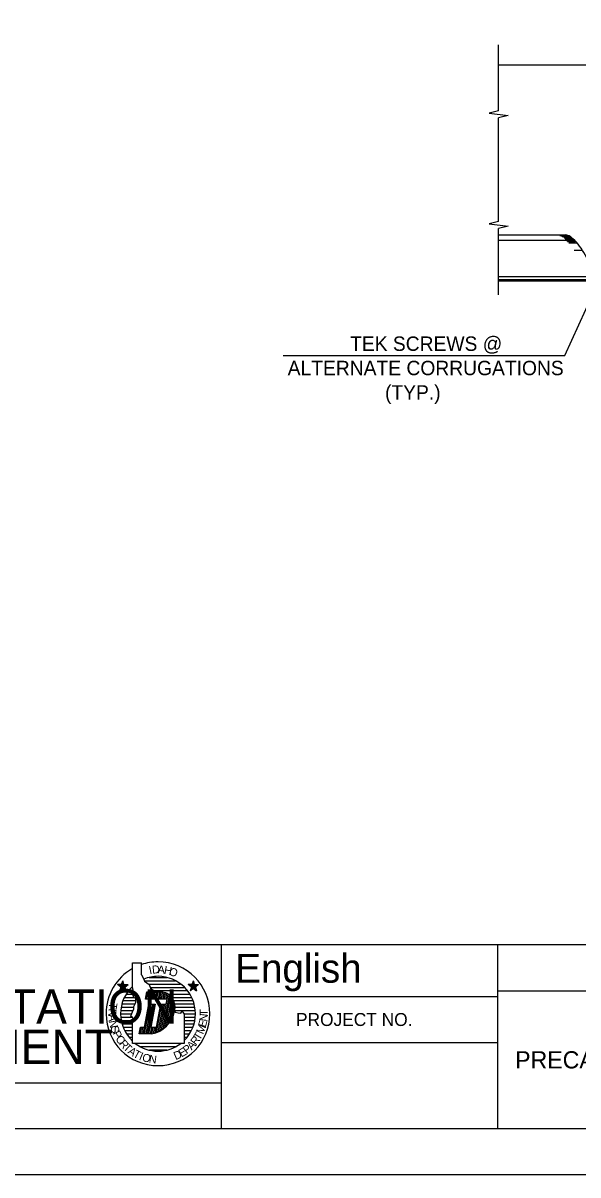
# Model space of a CAD drawing. Extents: x 0 to 34, y 0 to 23.5.
# Drawn here: x 17.1 to 23.12, y 0 to 12.5 of the extents above; entities that cross this region are included whole.
import ezdxf

# ---------------------------------------------------------------- set-up
doc = ezdxf.new("R2010")
doc.units = 0
for name, color, linetype in [('BORDER_ANNO_Cutsheet', 7, 'Continuous'), ('BRDG_ANNO_Anno-Sheet', 7, 'Continuous'), ('BRDG_ANNO_General-Notes', 7, 'Continuous'), ('BRDG_BASE_Obj-Line', 7, 'Continuous')]:
    doc.layers.add(name, color=color, linetype=linetype)

msp = doc.modelspace()

# ---------------------------------------------------------------- linework, layer by layer
at = {"layer": 'BORDER_ANNO_Cutsheet'}
msp.add_lwpolyline([(0, 22), (34, 22), (34, 0), (0, 0)], close=True, dxfattribs=at)
at = {"layer": 'BRDG_ANNO_Anno-Sheet'}
for p, q in [((1.5, 2.5), (19.25, 2.5)), ((19.25, 0.5), (19.25, 2.5)), ((19.25, 2.5), (33.5, 2.5)), ((22.25, 0.5), (22.25, 2.5)), ((18.284, 2.042), (18.284, 2.303)), ((18.284, 2.303), (18.383, 2.303)), ((18.383, 2.173), (18.383, 2.303)), ((18.383, 2.173), (18.409, 2.126)), ((18.409, 2.126), (18.414, 2.105)), ((18.465, 2.144), (18.658, 2.144)), ((18.201, 2.04), (18.122, 2.066)), ((18.166, 2.066), (18.122, 2.066)), ((18.157, 2.04), (18.122, 2.066)), ((18.193, 2.066), (18.144, 1.998)), ((18.157, 2.04), (18.144, 1.998)), ((18.179, 2.024), (18.144, 1.998)), ((18.157, 2.04), (18.237, 2.066)), ((18.166, 2.066), (18.179, 2.107)), ((18.166, 2.066), (18.215, 1.998)), ((18.179, 2.024), (18.179, 2.107)), ((18.193, 2.066), (18.179, 2.107)), ((18.179, 2.024), (18.215, 1.998)), ((18.193, 2.066), (18.237, 2.066)), ((18.201, 2.04), (18.237, 2.066)), ((18.201, 2.04), (18.215, 1.998)), ((18.242, 2.001), (18.294, 2.001)), ((18.274, 2.036), (18.286, 2.036)), ((18.294, 2.006), (18.284, 2.042)), ((18.294, 1.975), (18.294, 2.006)), ((18.414, 2.105), (18.466, 2.069)), ((18.417, 2.108), (18.751, 2.108)), ((18.465, 2.072), (18.807, 2.072)), ((18.466, 2.069), (18.482, 2.027)), ((18.479, 2.036), (18.851, 2.036)), ((18.482, 2.027), (18.534, 1.986)), ((18.516, 2.001), (18.883, 2.001)), ((18.968, 2.04), (18.888, 2.066)), ((18.924, 2.04), (18.888, 2.066)), ((18.932, 2.066), (18.888, 2.066)), ((18.959, 2.066), (18.91, 1.998)), ((18.924, 2.04), (18.91, 1.998)), ((18.946, 2.024), (18.91, 1.998)), ((18.924, 2.04), (19.002, 2.066)), ((18.932, 2.066), (18.946, 2.107)), ((18.932, 2.066), (18.981, 1.998)), ((18.946, 2.024), (18.946, 2.107)), ((18.959, 2.066), (18.946, 2.107)), ((18.946, 2.024), (18.981, 1.998)), ((18.959, 2.066), (19.002, 2.066)), ((18.968, 2.04), (19.002, 2.066)), ((18.968, 2.04), (18.981, 1.998)), ((18.181, 1.892), (18.319, 1.892)), ((18.197, 1.928), (18.298, 1.928)), ((18.217, 1.964), (18.293, 1.964)), ((18.294, 1.949), (18.294, 1.975)), ((18.3, 1.928), (18.294, 1.949)), ((18.321, 1.917), (18.3, 1.928)), ((18.31, 1.85), (18.321, 1.876)), ((18.321, 1.891), (18.321, 1.917)), ((18.321, 1.876), (18.321, 1.891)), ((18.425, 1.907), (18.441, 1.986)), ((18.661, 1.907), (18.425, 1.907)), ((18.439, 1.907), (18.454, 1.986)), ((18.441, 1.986), (18.613, 1.986)), ((18.455, 1.907), (18.47, 1.986)), ((18.471, 1.907), (18.486, 1.986)), ((18.487, 1.907), (18.502, 1.986)), ((18.502, 1.907), (18.517, 1.986)), ((18.519, 1.907), (18.533, 1.986)), ((18.534, 1.907), (18.549, 1.986)), ((18.551, 1.907), (18.565, 1.986)), ((18.566, 1.907), (18.581, 1.986)), ((18.582, 1.907), (18.597, 1.986)), ((18.598, 1.907), (18.613, 1.986)), ((18.599, 1.574), (18.672, 1.962)), ((18.614, 1.907), (18.628, 1.981)), ((18.617, 1.586), (18.686, 1.952)), ((18.63, 1.907), (18.643, 1.977)), ((18.636, 1.601), (18.699, 1.939)), ((18.646, 1.907), (18.657, 1.97)), ((18.652, 1.855), (18.661, 1.907)), ((18.656, 1.619), (18.712, 1.924)), ((18.669, 1.964), (18.907, 1.964)), ((18.676, 1.64), (18.725, 1.906)), ((18.697, 1.669), (18.737, 1.882)), ((18.71, 1.928), (18.927, 1.928)), ((18.732, 1.892), (18.943, 1.892)), ((19.25, 1.938), (22.25, 1.938)), ((22.25, 2), (30.25, 2)), ((18.157, 1.784), (18.291, 1.784)), ((18.162, 1.821), (18.298, 1.821)), ((18.171, 1.856), (18.311, 1.856)), ((18.269, 1.725), (18.279, 1.751)), ((18.279, 1.751), (18.284, 1.772)), ((18.284, 1.772), (18.3, 1.803)), ((18.3, 1.829), (18.31, 1.85)), ((18.3, 1.803), (18.3, 1.829)), ((18.414, 1.605), (18.461, 1.855)), ((18.416, 1.532), (18.477, 1.855)), ((18.433, 1.532), (18.493, 1.855)), ((18.448, 1.532), (18.509, 1.855)), ((18.461, 1.855), (18.53, 1.855)), ((18.464, 1.532), (18.525, 1.855)), ((18.53, 1.855), (18.483, 1.605)), ((18.544, 1.605), (18.591, 1.855)), ((18.547, 1.547), (18.604, 1.855)), ((18.564, 1.555), (18.62, 1.855)), ((18.581, 1.563), (18.636, 1.855)), ((18.591, 1.855), (18.652, 1.855)), ((18.722, 1.718), (18.746, 1.845)), ((18.741, 1.777), (18.748, 1.766)), ((18.742, 1.784), (18.968, 1.784)), ((18.744, 1.856), (18.954, 1.856)), ((18.747, 1.821), (18.962, 1.821)), ((18.748, 1.766), (18.779, 1.761)), ((18.779, 1.761), (18.811, 1.756)), ((18.811, 1.756), (18.826, 1.777)), ((18.826, 1.777), (18.847, 1.746)), ((18.156, 1.748), (18.277, 1.748)), ((18.158, 1.712), (18.281, 1.712)), ((18.163, 1.676), (18.298, 1.676)), ((18.171, 1.641), (18.284, 1.641)), ((18.284, 1.709), (18.269, 1.725)), ((18.294, 1.694), (18.284, 1.709)), ((18.284, 1.652), (18.3, 1.667)), ((18.284, 1.427), (18.284, 1.652)), ((18.3, 1.683), (18.294, 1.694)), ((18.3, 1.667), (18.3, 1.683)), ((18.845, 1.748), (18.969, 1.748)), ((18.847, 1.746), (18.847, 1.427)), ((18.847, 1.676), (18.962, 1.676)), ((18.847, 1.641), (18.954, 1.641)), ((18.848, 1.712), (18.967, 1.712)), ((18.184, 1.604), (18.282, 1.604)), ((18.199, 1.568), (18.282, 1.568)), ((18.22, 1.532), (18.283, 1.532)), ((18.359, 1.532), (18.373, 1.605)), ((18.492, 1.532), (18.359, 1.532)), ((18.369, 1.532), (18.383, 1.605)), ((18.373, 1.605), (18.414, 1.605)), ((18.385, 1.532), (18.399, 1.605)), ((18.401, 1.532), (18.414, 1.605)), ((18.48, 1.532), (18.494, 1.605)), ((18.483, 1.605), (18.544, 1.605)), ((18.496, 1.532), (18.51, 1.605)), ((18.513, 1.537), (18.526, 1.605)), ((18.53, 1.542), (18.541, 1.605)), ((18.847, 1.604), (18.941, 1.604)), ((18.847, 1.568), (18.925, 1.568)), ((18.847, 1.532), (18.905, 1.532)), ((18.246, 1.496), (18.282, 1.496)), ((18.277, 1.461), (18.284, 1.461)), ((18.847, 1.427), (18.284, 1.427)), ((18.751, 1.391), (18.372, 1.391)), ((18.847, 1.496), (18.88, 1.496)), ((19.25, 1.438), (22.25, 1.438)), ((18.659, 1.356), (18.468, 1.356)), ((14, 1), (19.25, 1))]:
    msp.add_line(p, q, dxfattribs=at)
msp.add_lwpolyline([(1.5, 21.5), (33.5, 21.5), (33.5, 0.5), (1.5, 0.5)], close=True, dxfattribs=at)
for centre, radius, start, end in [((18.562, 1.75), 0.563, 90, 108.596), ((18.562, 1.75), 0.563, 0, 90), ((18.562, 1.75), 0.563, 119.6331, 180), ((18.562, 1.75), 0.406, 90, 112.1452), ((18.562, 1.75), 0.406, 0, 90), ((18.562, 1.75), 0.406, 133.1926, 180), ((18.583, 1.824), 0.164, 343.4981, 79.7362), ((18.435, 1.838), 0.312, 280.6479, 348.7719), ((18.562, 1.75), 0.563, 180, 270), ((18.562, 1.75), 0.406, 180.2644, 226.7946), ((18.562, 1.75), 0.563, 270, 0), ((18.562, 1.75), 0.406, 314.427, 0), ((18.562, 1.75), 0.406, 232.5658, 270), ((18.562, 1.75), 0.406, 270, 307.4536)]:
    msp.add_arc(centre, radius, start, end, dxfattribs=at)
at = {"layer": 'BRDG_ANNO_General-Notes'}
for p, q in [((22.976, 8.893), (23.281, 9.56)), ((19.92, 8.893), (22.976, 8.893))]:
    msp.add_line(p, q, dxfattribs=at)
at = {"layer": 'BRDG_BASE_Obj-Line'}
for p, q in [((22.258, 11.551), (22.258, 12.267)), ((22.258, 12.05), (26.139, 12.05)), ((22.258, 11.551), (22.156, 11.525)), ((22.156, 11.525), (22.361, 11.5)), ((22.361, 11.5), (22.258, 11.474)), ((22.258, 10.348), (22.258, 11.474)), ((22.258, 10.348), (22.156, 10.323)), ((22.156, 10.323), (22.361, 10.297)), ((22.361, 10.297), (22.258, 10.272)), ((22.258, 9.555), (22.258, 10.272)), ((22.258, 10.205), (22.985, 10.205)), ((22.258, 10.148), (23.077, 10.148)), ((22.922, 10.197), (23.003, 10.197)), ((22.936, 10.192), (23.018, 10.192)), ((22.946, 10.187), (23.03, 10.187)), ((22.964, 10.18), (23.047, 10.18)), ((22.974, 10.17), (23.057, 10.17)), ((22.979, 10.162), (23.062, 10.162)), ((22.988, 10.156), (23.072, 10.156)), ((22.998, 10.141), (23.079, 10.141)), ((23.005, 10.133), (23.089, 10.133)), ((23.02, 10.118), (23.104, 10.118)), ((23.077, 10.039), (23.161, 10.039)), ((22.258, 9.752), (23.382, 9.752)), ((22.258, 9.718), (23.515, 9.718)), ((22.258, 9.705), (23.515, 9.705))]:
    msp.add_line(p, q, dxfattribs=at)
msp.add_spline([(23.515, 9.718), (23.473, 9.724), (23.441, 9.729), (23.392, 9.747), (23.343, 9.791), (23.195, 9.988), (23.136, 10.082), (23.064, 10.162), (23.033, 10.187), (22.985, 10.205)], degree=3, dxfattribs=at)

# ---------------------------------------------------------------- texts
at = {"layer": 'BRDG_ANNO_Anno-Sheet'}
for s, height, p in [('English', 0.3125, (19.401, 2.087)), ('TRANSPORTATION', 0.375, (14.147, 1.641)), ('PROJECT NO.', 0.14062, (20.059, 1.617)), ('DEPARTMENT', 0.375, (14.619, 1.203)), ('PRECAST/PRESTRESSED CONCRETE GIRDER BRIDGE', 0.1875, (22.437, 1.156))]:
    msp.add_text(s, height=height, dxfattribs=at).set_placement(p)
for s, rotation, p in [('I', 11.9519, (18.472, 2.178)), ('D', 5.2118, (18.501, 2.184)), ('A', 357.8718, (18.557, 2.188)), ('H', 349.6318, (18.622, 2.184)), ('O', 342.1917, (18.674, 2.173)), ('R', 266.0275, (18.026, 1.807)), ('T', 259.4265, (18.038, 1.876)), ('T', 90.4926, (19.102, 1.729)), ('A', 273.764, (18.023, 1.741)), ('N', 280.3758, (18.029, 1.671)), ('M', 67.7139, (19.051, 1.521)), ('E', 75.6105, (19.079, 1.597)), ('N', 83.1932, (19.095, 1.663)), ('S', 287.9279, (18.043, 1.604)), ('P', 295.4976, (18.066, 1.541)), ('O', 302.6446, (18.096, 1.48)), ('R', 52.3344, (18.974, 1.401)), ('T', 59.0362, (19.014, 1.455)), ('R', 309.9079, (18.134, 1.422)), ('T', 317.1211, (18.177, 1.371)), ('A', 324.6375, (18.228, 1.326)), ('E', 30.5476, (18.816, 1.274)), ('P', 37.6656, (18.873, 1.309)), ('A', 45, (18.926, 1.351)), ('T', 331.7503, (18.284, 1.287)), ('I', 337.0213, (18.349, 1.254)), ('O', 343.3287, (18.383, 1.241)), ('N', 351.6598, (18.459, 1.22)), ('D', 22.9887, (18.753, 1.246))]:
    msp.add_text(s, height=0.0869, rotation=rotation, dxfattribs=at).set_placement(p)
at = {"layer": 'BRDG_ANNO_General-Notes'}
for s, height, p in [('TEK SCREWS @', 0.15622, (20.646, 8.945)), ('ALTERNATE CORRUGATIONS', 0.15622, (19.969, 8.681)), ('(TYP.)', 0.1562, (21.025, 8.416))]:
    msp.add_text(s, height=height, dxfattribs=at).set_placement(p)

doc.saveas('drawing.dxf')
